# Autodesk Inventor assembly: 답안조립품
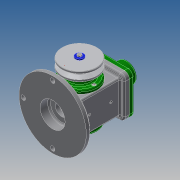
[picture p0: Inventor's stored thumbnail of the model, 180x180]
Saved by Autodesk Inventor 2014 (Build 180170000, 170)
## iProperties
Created: 2019-08
Part Number: 답안조립품
Document SubType Name: Assembly
Designer: kb542
Author: kb542
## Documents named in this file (18)
- C:\Users\kb542\Desktop\490804V1033\답안조립품.iam
- C:\Users\kb542\Desktop\490804V1033\본체.ipt
- C:\Users\kb542\Desktop\490804V1033\E-링.ipt
- C:\Users\kb542\Desktop\490804V1033\V-벨트풀리.ipt
- C:\Users\kb542\Desktop\490804V1033\덮개.ipt
- C:\Users\kb542\Desktop\490804V1033\뒤커버.ipt
- C:\Users\kb542\Desktop\490804V1033\링크.ipt
- C:\Users\kb542\Desktop\490804V1033\베어링 17 x 40 x 12.ipt
- C:\Users\kb542\Desktop\490804V1033\볼트 M4 x 8.ipt
- C:\Users\kb542\Desktop\490804V1033\볼트 M4 x 10.ipt
- C:\Users\kb542\Desktop\490804V1033\슬라이더.ipt
- C:\Users\kb542\Desktop\490804V1033\앞커버.ipt
- C:\Users\kb542\Desktop\490804V1033\오일 실 17 30 8.ipt
- C:\Users\kb542\Desktop\490804V1033\와셔 4x16.ipt
- C:\Users\kb542\Desktop\490804V1033\클레비스 핀 6 x 22.ipt
- 클레비스 핀 6 x 22.ipt
- C:\Users\kb542\Desktop\490804V1033\키 4 x 4 x 12.ipt
- C:\Users\kb542\Desktop\490804V1033\편심축.ipt
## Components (2 placed, 2 different names)
1. E-링:1 — 각도:1
2. V-벨트풀리:1
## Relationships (1: Angle 1)
- 각도:1 [Angle]: E-링:1
